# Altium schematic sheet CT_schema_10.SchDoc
size 281 x 153 mm
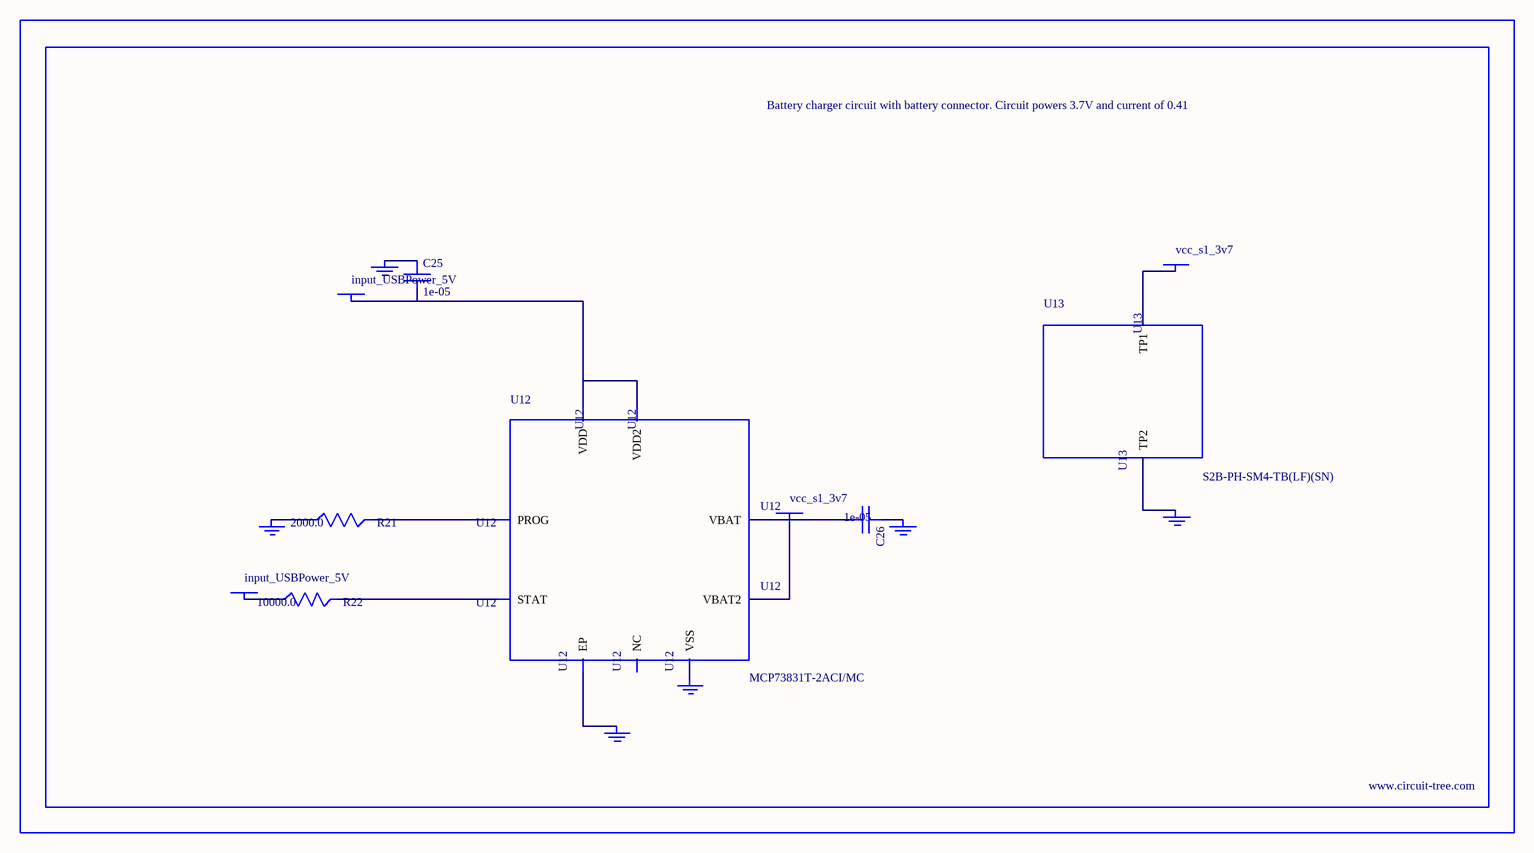
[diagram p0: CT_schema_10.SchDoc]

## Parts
BORDER9  (no value)
C25  1e-05  [C1206]
C26  1e-05  [C1206]
GND_INSTANCE_9_0  (no value)
GND_INSTANCE_9_1  (no value)
GND_INSTANCE_9_2  (no value)
GND_INSTANCE_9_3  (no value)
GND_INSTANCE_9_4  (no value)
GND_INSTANCE_9_5  (no value)
POWER_INSTANCE_9_0  input_USBPower_5V
POWER_INSTANCE_9_1  input_USBPower_5V
POWER_INSTANCE_9_2  vcc_s1_3v7
POWER_INSTANCE_9_3  vcc_s1_3v7
R21  2000.0  [R0603]
R22  10000.0  [R0603]
U12  MCP73831T-2ACI/MC  [DFN8_2X3MC]
U13  S2B-PH-SM4-TB(LF)(SN)  [JST-2-SMD]

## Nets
NetC25_1: C25.1 GND_INSTANCE_9_0.0(GND)
NetC25_2: C25.2 POWER_INSTANCE_9_0.0(PWR) U12.1(VDD) U12.2(VDD2)
NetC26_1: C26.1 GND_INSTANCE_9_1.0(GND)
NetC26_2: C26.2 POWER_INSTANCE_9_2.0(PWR) U12.3(VBAT) U12.4(VBAT2)
NetGND_INSTANCE_9_2_0: GND_INSTANCE_9_2.0(GND) R21.1
NetGND_INSTANCE_9_3_0: GND_INSTANCE_9_3.0(GND) U12.9(EP)
NetGND_INSTANCE_9_4_0: GND_INSTANCE_9_4.0(GND) U12.6(VSS)
NetGND_INSTANCE_9_5_0: GND_INSTANCE_9_5.0(GND) U13.2(TP2)
NetPOWER_INSTANCE_9_1_0: POWER_INSTANCE_9_1.0(PWR) R22.1
NetPOWER_INSTANCE_9_3_0: POWER_INSTANCE_9_3.0(PWR) U13.1(TP1)
NetR21_2: R21.2 U12.8(PROG)
NetR22_2: R22.2 U12.5(STAT)

Not connected (* = marked no-connect by the designer): U12 7(NC)

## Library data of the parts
BORDER9 = BORDER_PAGE9
C25 C26 = C1206C106K3RACTU
GND_INSTANCE_9_0-GND_INSTANCE_9_5 = GND
POWER_INSTANCE_9_0-POWER_INSTANCE_9_3 = PWR
R21 = RC0603JR-072KL
R22 = RC0603JR-0710KL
